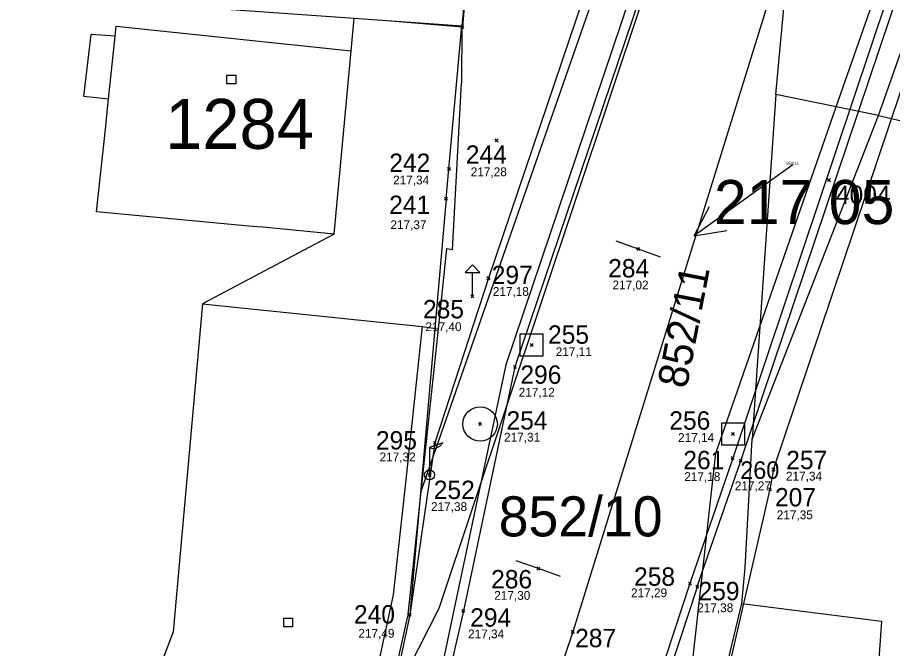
# Model space of a CAD drawing. Extents: x -711879 to -711361, y -1048782 to -1048177.
# Drawn here: x -711653.59 to -711623.84, y -1048502.22 to -1048480.75 of the extents above; entities that cross this region are included whole.
import ezdxf

# ---------------------------------------------------------------- set-up
doc = ezdxf.new("R2010")
doc.units = 0
for name, color, linetype in [('body', 7, 'Continuous'), ('kresba', 7, 'Continuous'), ('Vrstva 1', 7, 'Continuous'), ('Vrstva 13', 7, 'Continuous'), ('Vrstva 14', 7, 'Continuous'), ('Vrstva 15', 7, 'Continuous'), ('Vrstva 16', 7, 'Continuous'), ('Vrstva 2', 7, 'Continuous'), ('Vrstva 20', 7, 'Continuous'), ('Vrstva 25', 7, 'Continuous'), ('Vrstva 41', 7, 'Continuous'), ('Vrstva 46', 7, 'Continuous'), ('výšky', 7, 'Continuous')]:
    doc.layers.add(name, color=color, linetype=linetype)

msp = doc.modelspace()

# ---------------------------------------------------------------- linework, layer by layer
at = {"layer": 'kresba'}
for p, q in [((-711627.89, -1048496.13), (-711612.41, -1048450.08)), ((-711632.11, -1048473.45), (-711637.58, -1048489.62)), ((-711630.53, -1048473.44), (-711636.99, -1048492.57)), ((-711630.22, -1048473.51), (-711636.68, -1048492.64)), ((-711632.48, -1048488.63), (-711633.23, -1048488.36)), ((-711631.73, -1048488.9), (-711632.48, -1048488.63)), ((-711637.58, -1048489.62), (-711639.4, -1048495.22)), ((-711636.99, -1048492.57), (-711638.74, -1048500.86)), ((-711636.68, -1048492.64), (-711638.43, -1048500.93)), ((-711639.4, -1048495.22), (-711640.25, -1048501.07)), ((-711639.58, -1048495.38), (-711639.58, -1048496.31)), ((-711629.27, -1048495.74), (-711630.73, -1048500.01)), ((-711627.89, -1048496.13), (-711628.01, -1048496.8)), ((-711628.01, -1048496.8), (-711629.97, -1048505.32)), ((-711635.88, -1048499.5), (-711636.63, -1048499.23)), ((-711635.13, -1048499.77), (-711635.88, -1048499.5)), ((-711638.74, -1048500.86), (-711639.9, -1048506.25)), ((-711638.43, -1048500.93), (-711639.65, -1048506.31))]:
    msp.add_line(p, q, dxfattribs=at)
for points in [[(-711630.48, -1048500.11), (-711629, -1048495.83), (-711614.47, -1048452.67), (-711599.94, -1048409.51)], [(-711617.94, -1048449.74), (-711626.67, -1048475.73), (-711634.71, -1048501.65), (-711638.73, -1048513.57), (-711639.471, -1048515.651)], [(-711614.77, -1048452.56), (-711623.43, -1048478.33), (-711629.27, -1048495.74)], [(-711639.02, -1048486.92), (-711640.25, -1048501.07), (-711640.93, -1048504.26), (-711645.49, -1048516.28), (-711647.09, -1048518.67), (-711649.95, -1048521.15)], [(-711638.12, -1048490.24), (-711638.12, -1048489.42), (-711637.87, -1048489.42), (-711638.12, -1048489.17), (-711638.37, -1048489.42), (-711638.12, -1048489.42)], [(-711630.73, -1048500.01), (-711637.6, -1048520.9), (-711636.56, -1048522.97)], [(-711630.475, -1048500.094), (-711637.31, -1048520.879), (-711636.32, -1048522.849)]]:
    msp.add_lwpolyline(points, dxfattribs=at)
for points in [[(-711636.495, -1048491.51), (-711635.725, -1048491.51), (-711635.725, -1048492.27), (-711636.495, -1048492.27)], [(-711629.645, -1048494.54), (-711628.875, -1048494.54), (-711628.875, -1048495.3), (-711629.645, -1048495.3)], [(-711639.58, -1048495.38), (-711639.48, -1048495.41), (-711639.35, -1048495.39), (-711639.23, -1048495.33), (-711639.13, -1048495.22)]]:
    msp.add_lwpolyline(points, close=True, dxfattribs=at)
for centre, radius in [((-711637.86, -1048494.58), 0.585), ((-711639.58, -1048496.31), 0.17)]:
    msp.add_circle(centre, radius, dxfattribs=at)
at = {"layer": 'Vrstva 1'}
for p, q in [((-711625.12, -1048454.55), (-711639.88, -1048496.88)), ((-711624.32, -1048484.08), (-711615.16, -1048458.11)), ((-711627.81, -1048483.37), (-711625.64, -1048460.08)), ((-711637.08, -1048465.05), (-711638.48, -1048481.03)), ((-711648.41, -1048480.33), (-711642.14, -1048480.77)), ((-711642.25, -1048481.89), (-711642.14, -1048480.77)), ((-711650.27, -1048481.39), (-711650.23, -1048481.05)), ((-711650.23, -1048481.05), (-711642.25, -1048481.89)), ((-711638.48, -1048481.03), (-711638.49, -1048482.99)), ((-711651.33, -1048483.44), (-711651.09, -1048481.33)), ((-711650.27, -1048481.39), (-711651.09, -1048481.33)), ((-711642.82, -1048488.12), (-711642.25, -1048481.89)), ((-711638.8, -1048488.65), (-711638.49, -1048482.99)), ((-711650.5, -1048483.53), (-711651.33, -1048483.44)), ((-711650.53, -1048483.85), (-711650.5, -1048483.53)), ((-711627.81, -1048483.37), (-711628.35, -1048491.26)), ((-711625.75, -1048483.79), (-711627.81, -1048483.37)), ((-711650.59, -1048484.45), (-711650.53, -1048483.85)), ((-711624.32, -1048484.08), (-711625.75, -1048483.79)), ((-711628.61, -1048495.1), (-711624.32, -1048484.08)), ((-711624.32, -1048484.08), (-711613.91, -1048486.53)), ((-711650.9, -1048487.36), (-711650.59, -1048484.45)), ((-711645.72, -1048487.85), (-711650.9, -1048487.36)), ((-711645.12, -1048487.9), (-711645.72, -1048487.85)), ((-711642.82, -1048488.12), (-711645.12, -1048487.9)), ((-711643.08, -1048488.26), (-711647.3, -1048490.49)), ((-711642.82, -1048488.12), (-711643.08, -1048488.26)), ((-711639, -1048488.62), (-711639.29, -1048491.34)), ((-711638.8, -1048488.65), (-711639, -1048488.62)), ((-711647.3, -1048490.49), (-711648.3, -1048501.65)), ((-711628.35, -1048491.26), (-711628.61, -1048495.1)), ((-711639.29, -1048491.34), (-711639.88, -1048496.88)), ((-711628.85, -1048499.46), (-711628.61, -1048495.1)), ((-711639.88, -1048496.88), (-711640.33, -1048501.16)), ((-711628.96, -1048500.69), (-711628.85, -1048499.46)), ((-711629.99, -1048504.96), (-711628.96, -1048500.69)), ((-711641.02, -1048504.29), (-711640.33, -1048501.16)), ((-711648.3, -1048501.65), (-711653.59, -1048515.69))]:
    msp.add_line(p, q, dxfattribs=at)
at = {"layer": 'Vrstva 13'}
msp.add_line((-711627.23, -1048485.76), (-711628.15, -1048486.42), dxfattribs=at)
at = {"layer": 'Vrstva 16'}
for p, q in [((-711628.15, -1048486.42), (-711630.581, -1048488.176)), ((-711630.581, -1048488.176), (-711630.064, -1048487.185)), ((-711630.581, -1048488.176), (-711629.478, -1048487.996))]:
    msp.add_line(p, q, dxfattribs=at)
at = {"layer": 'Vrstva 2'}
for p, q in [((-711625.75, -1048483.79), (-711616.62, -1048457.59)), ((-711625.64, -1048460.08), (-711639.27, -1048500.86)), ((-711642.14, -1048480.77), (-711638.48, -1048481.03)), ((-711650.5, -1048483.53), (-711650.27, -1048481.39)), ((-711628.35, -1048491.26), (-711625.75, -1048483.79)), ((-711647.3, -1048490.49), (-711639.83, -1048491.26)), ((-711639.83, -1048491.26), (-711640.4, -1048496.58)), ((-711639.83, -1048491.26), (-711639.29, -1048491.34)), ((-711629.85, -1048495.57), (-711628.35, -1048491.26)), ((-711631.25, -1048508.18), (-711629.85, -1048495.57)), ((-711640.4, -1048496.58), (-711640.82, -1048500.39)), ((-711640.82, -1048500.39), (-711641.58, -1048503.95)), ((-711628.96, -1048500.69), (-711624.21, -1048501.29)), ((-711639.27, -1048500.86), (-711641.02, -1048504.29)), ((-711624.21, -1048501.29), (-711624.54, -1048505.69))]:
    msp.add_line(p, q, dxfattribs=at)
at = {"layer": 'Vrstva 20'}
for p, q in [((-711638.46, -1048481.08), (-711638.51, -1048481.03)), ((-711638.46, -1048481.08), (-711638.51, -1048481.13)), ((-711638.46, -1048481.08), (-711638.41, -1048481.03)), ((-711638.46, -1048481.08), (-711638.41, -1048481.13)), ((-711637.3, -1048484.93), (-711637.35, -1048484.88)), ((-711637.3, -1048484.93), (-711637.35, -1048484.98)), ((-711637.3, -1048484.93), (-711637.25, -1048484.88)), ((-711637.3, -1048484.93), (-711637.25, -1048484.98)), ((-711638.92, -1048485.9), (-711638.97, -1048485.85)), ((-711638.92, -1048485.9), (-711638.97, -1048485.95)), ((-711638.92, -1048485.9), (-711638.87, -1048485.85)), ((-711638.92, -1048485.9), (-711638.87, -1048485.95)), ((-711626, -1048486.28), (-711626.05, -1048486.23)), ((-711626, -1048486.28), (-711625.95, -1048486.23)), ((-711626, -1048486.28), (-711626.05, -1048486.33)), ((-711626, -1048486.28), (-711625.95, -1048486.33)), ((-711639.02, -1048486.92), (-711639.07, -1048486.87)), ((-711639.02, -1048486.92), (-711639.07, -1048486.97)), ((-711639.02, -1048486.92), (-711638.97, -1048486.87)), ((-711639.02, -1048486.92), (-711638.97, -1048486.97)), ((-711632.48, -1048488.63), (-711632.53, -1048488.58)), ((-711632.48, -1048488.63), (-711632.53, -1048488.68)), ((-711632.48, -1048488.63), (-711632.43, -1048488.58)), ((-711632.48, -1048488.63), (-711632.43, -1048488.68)), ((-711637.58, -1048489.62), (-711637.63, -1048489.57)), ((-711637.58, -1048489.62), (-711637.63, -1048489.67)), ((-711637.58, -1048489.62), (-711637.53, -1048489.57)), ((-711637.58, -1048489.62), (-711637.53, -1048489.67)), ((-711638.12, -1048490.24), (-711638.17, -1048490.19)), ((-711638.12, -1048490.24), (-711638.17, -1048490.29)), ((-711638.12, -1048490.24), (-711638.07, -1048490.19)), ((-711638.12, -1048490.24), (-711638.07, -1048490.29)), ((-711636.11, -1048491.89), (-711636.16, -1048491.84)), ((-711636.11, -1048491.89), (-711636.16, -1048491.94)), ((-711636.11, -1048491.89), (-711636.06, -1048491.84)), ((-711636.11, -1048491.89), (-711636.06, -1048491.94)), ((-711636.68, -1048492.64), (-711636.73, -1048492.59)), ((-711636.68, -1048492.64), (-711636.73, -1048492.69)), ((-711636.68, -1048492.64), (-711636.63, -1048492.59)), ((-711636.68, -1048492.64), (-711636.63, -1048492.69)), ((-711637.86, -1048494.58), (-711637.91, -1048494.53)), ((-711637.86, -1048494.58), (-711637.91, -1048494.63)), ((-711637.86, -1048494.58), (-711637.81, -1048494.53)), ((-711637.86, -1048494.58), (-711637.81, -1048494.63)), ((-711629.26, -1048494.92), (-711629.31, -1048494.87)), ((-711629.26, -1048494.92), (-711629.21, -1048494.87)), ((-711639.4, -1048495.22), (-711639.45, -1048495.17)), ((-711639.4, -1048495.22), (-711639.35, -1048495.17)), ((-711629.26, -1048494.92), (-711629.31, -1048494.97)), ((-711629.26, -1048494.92), (-711629.21, -1048494.97)), ((-711639.4, -1048495.22), (-711639.45, -1048495.27)), ((-711639.4, -1048495.22), (-711639.35, -1048495.27)), ((-711629.27, -1048495.74), (-711629.32, -1048495.69)), ((-711629.27, -1048495.74), (-711629.32, -1048495.79)), ((-711629.27, -1048495.74), (-711629.22, -1048495.69)), ((-711629.27, -1048495.74), (-711629.22, -1048495.79)), ((-711629, -1048495.83), (-711629.05, -1048495.78)), ((-711629, -1048495.83), (-711628.95, -1048495.78)), ((-711629, -1048495.83), (-711629.05, -1048495.88)), ((-711629, -1048495.83), (-711628.95, -1048495.88)), ((-711627.89, -1048496.13), (-711627.94, -1048496.08)), ((-711627.89, -1048496.13), (-711627.84, -1048496.08)), ((-711639.58, -1048496.31), (-711639.63, -1048496.26)), ((-711639.58, -1048496.31), (-711639.63, -1048496.36)), ((-711639.58, -1048496.31), (-711639.53, -1048496.26)), ((-711639.58, -1048496.31), (-711639.53, -1048496.36)), ((-711627.89, -1048496.13), (-711627.94, -1048496.18)), ((-711627.89, -1048496.13), (-711627.84, -1048496.18)), ((-711628.01, -1048496.8), (-711628.06, -1048496.75)), ((-711628.01, -1048496.8), (-711628.06, -1048496.85)), ((-711628.01, -1048496.8), (-711627.96, -1048496.75)), ((-711628.01, -1048496.8), (-711627.96, -1048496.85)), ((-711635.88, -1048499.5), (-711635.93, -1048499.45)), ((-711635.88, -1048499.5), (-711635.93, -1048499.55)), ((-711635.88, -1048499.5), (-711635.83, -1048499.45)), ((-711635.88, -1048499.5), (-711635.83, -1048499.55)), ((-711630.73, -1048500.01), (-711630.78, -1048499.96)), ((-711630.73, -1048500.01), (-711630.78, -1048500.06)), ((-711630.73, -1048500.01), (-711630.68, -1048499.96)), ((-711630.73, -1048500.01), (-711630.68, -1048500.06)), ((-711630.48, -1048500.11), (-711630.53, -1048500.06)), ((-711630.48, -1048500.11), (-711630.53, -1048500.16)), ((-711630.48, -1048500.11), (-711630.43, -1048500.06)), ((-711630.48, -1048500.11), (-711630.43, -1048500.16)), ((-711640.25, -1048501.07), (-711640.3, -1048501.02)), ((-711640.25, -1048501.07), (-711640.3, -1048501.12)), ((-711640.25, -1048501.07), (-711640.2, -1048501.02)), ((-711640.25, -1048501.07), (-711640.2, -1048501.12)), ((-711638.43, -1048500.93), (-711638.48, -1048500.88)), ((-711638.43, -1048500.93), (-711638.48, -1048500.98)), ((-711638.43, -1048500.93), (-711638.38, -1048500.88)), ((-711638.43, -1048500.93), (-711638.38, -1048500.98)), ((-711634.71, -1048501.65), (-711634.76, -1048501.6)), ((-711634.71, -1048501.65), (-711634.76, -1048501.7)), ((-711634.71, -1048501.65), (-711634.66, -1048501.6)), ((-711634.71, -1048501.65), (-711634.66, -1048501.7))]:
    msp.add_line(p, q, dxfattribs=at)
at = {"layer": 'Vrstva 25'}
for p, q in [((-711646.47, -1048482.71), (-711646.17, -1048482.71)), ((-711646.47, -1048483.01), (-711646.47, -1048482.71)), ((-711646.17, -1048482.71), (-711646.17, -1048483.01)), ((-711646.17, -1048483.01), (-711646.47, -1048483.01)), ((-711644.54, -1048501.18), (-711644.24, -1048501.18)), ((-711644.54, -1048501.48), (-711644.54, -1048501.18)), ((-711644.24, -1048501.18), (-711644.24, -1048501.48)), ((-711644.24, -1048501.48), (-711644.54, -1048501.48))]:
    msp.add_line(p, q, dxfattribs=at)
at = {"layer": 'Vrstva 41'}
for p, q in [((-711638.46, -1048481.08), (-711638.46, -1048481.08)), ((-711637.3, -1048484.93), (-711637.3, -1048484.93)), ((-711638.92, -1048485.9), (-711638.92, -1048485.9)), ((-711626, -1048486.28), (-711626, -1048486.28)), ((-711639.02, -1048486.92), (-711639.02, -1048486.92)), ((-711632.48, -1048488.63), (-711632.48, -1048488.63)), ((-711637.58, -1048489.62), (-711637.58, -1048489.62)), ((-711638.12, -1048490.24), (-711638.12, -1048490.24)), ((-711636.11, -1048491.89), (-711636.11, -1048491.89)), ((-711636.68, -1048492.64), (-711636.68, -1048492.64)), ((-711637.86, -1048494.58), (-711637.86, -1048494.58)), ((-711629.26, -1048494.92), (-711629.26, -1048494.92)), ((-711639.4, -1048495.22), (-711639.4, -1048495.22)), ((-711629.27, -1048495.74), (-711629.27, -1048495.74)), ((-711629, -1048495.83), (-711629, -1048495.83)), ((-711639.58, -1048496.31), (-711639.58, -1048496.31)), ((-711627.89, -1048496.13), (-711627.89, -1048496.13)), ((-711628.01, -1048496.8), (-711628.01, -1048496.8)), ((-711635.88, -1048499.5), (-711635.88, -1048499.5)), ((-711630.73, -1048500.01), (-711630.73, -1048500.01)), ((-711630.48, -1048500.11), (-711630.48, -1048500.11)), ((-711640.25, -1048501.07), (-711640.25, -1048501.07)), ((-711638.43, -1048500.93), (-711638.43, -1048500.93)), ((-711634.71, -1048501.65), (-711634.71, -1048501.65))]:
    msp.add_line(p, q, dxfattribs=at)
at = {"layer": 'Vrstva 46'}
for p, q in [((-711650.23, -1048481.05), (-711650.23, -1048481.05)), ((-711638.92, -1048485.9), (-711638.48, -1048481.03)), ((-711650.53, -1048483.85), (-711650.53, -1048483.85)), ((-711650.59, -1048484.45), (-711650.59, -1048484.45)), ((-711639.02, -1048486.92), (-711638.92, -1048485.9)), ((-711650.9, -1048487.36), (-711650.9, -1048487.36)), ((-711645.72, -1048487.85), (-711645.72, -1048487.85)), ((-711645.12, -1048487.9), (-711645.12, -1048487.9)), ((-711642.82, -1048488.12), (-711642.82, -1048488.12)), ((-711639.83, -1048491.26), (-711639.83, -1048491.26)), ((-711628.85, -1048499.46), (-711628.85, -1048499.46)), ((-711624.21, -1048501.29), (-711624.21, -1048501.29))]:
    msp.add_line(p, q, dxfattribs=at)
msp.add_lwpolyline([(-711637.15, -1048465.26), (-711638.46, -1048481.08), (-711641.17, -1048480.856)], dxfattribs=at)

# ---------------------------------------------------------------- texts
at = {"layer": 'body'}
for s, height, p in [('242', 0.625, (-711640.949, -1048486.005)), ('244', 0.625, (-711638.348, -1048485.727)), ('4004', 0.625, (-711625.765, -1048487.094)), ('241', 0.625, (-711640.954, -1048487.435)), ('297', 0.625, (-711637.466, -1048489.821)), ('284', 0.625, (-711633.508, -1048489.593)), ('285', 0.625, (-711639.804, -1048490.986)), ('255', 0.625, (-711635.552, -1048491.85)), ('296', 0.625, (-711636.492, -1048493.212)), ('254', 0.625, (-711636.963, -1048494.768)), ('256', 0.625, (-711631.429, -1048494.772)), ('295', 0.625, (-711641.403, -1048495.447)), ('261', 0.625, (-711630.952, -1048496.117)), ('257', 0.625, (-711627.453, -1048496.116)), ('260', 0.5955, (-711629.017, -1048496.446)), ('252', 0.625, (-711639.437, -1048497.132)), ('207', 0.625, (-711627.835, -1048497.383)), ('286', 0.625, (-711637.487, -1048500.171)), ('258', 0.625, (-711632.627, -1048500.082)), ('259', 0.625, (-711630.434, -1048500.575)), ('240', 0.625, (-711642.151, -1048501.366)), ('294', 0.625, (-711638.198, -1048501.473)), ('287', 0.625, (-711634.631, -1048502.172))]:
    msp.add_text(s, height=height, dxfattribs=at).set_placement(p)
at = {"layer": 'kresba'}
msp.add_text('217,40', height=0.3, dxfattribs=at).set_placement((-711639.72, -1048491.42))
at = {"layer": 'Vrstva 14'}
for s, height, p in [('852/11', 0.1, (-711627.451, -1048485.76)), ('852/10', 1.3627, (-711637.23, -1048498.403))]:
    msp.add_text(s, height=height, dxfattribs=at).set_placement(p)
at = {"layer": 'Vrstva 15'}
msp.add_text('1284', height=1.7, dxfattribs=at).set_placement((-711648.57, -1048485.22))
at = {"layer": 'Vrstva 16'}
msp.add_text('852/11', height=1.0203, rotation=79.0943, dxfattribs=at).set_placement((-711630.838, -1048493.403))
at = {"layer": 'Vrstva 20'}
msp.add_text('217 05 ', height=1.5, dxfattribs=at).set_placement((-711629.91, -1048487.78))
at = {"layer": 'výšky'}
for s, p in [('217,28', (-711638.18, -1048486.15)), ('217,34', (-711640.82, -1048486.43)), ('217,37', (-711640.91, -1048487.95)), ('217,02', (-711633.36, -1048490)), ('217,18', (-711637.43, -1048490.22)), ('217,11', (-711635.29, -1048492.27)), ('217,12', (-711636.55, -1048493.65)), ('217,31', (-711637.047, -1048495.178)), ('217,14', (-711631.13, -1048495.19)), ('217,32', (-711641.28, -1048495.85)), ('217,18', (-711630.92, -1048496.52)), ('217,34', (-711627.462, -1048496.502)), ('217,27', (-711629.2, -1048496.83)), ('217,38', (-711639.53, -1048497.54)), ('217,35', (-711627.775, -1048497.818)), ('217,29', (-711632.73, -1048500.47)), ('217,30', (-711637.38, -1048500.56)), ('217,38', (-711630.48, -1048500.98)), ('217,49', (-711642, -1048501.85)), ('217,34', (-711638.27, -1048501.87))]:
    msp.add_text(s, height=0.3, dxfattribs=at).set_placement(p)

doc.saveas('drawing.dxf')
